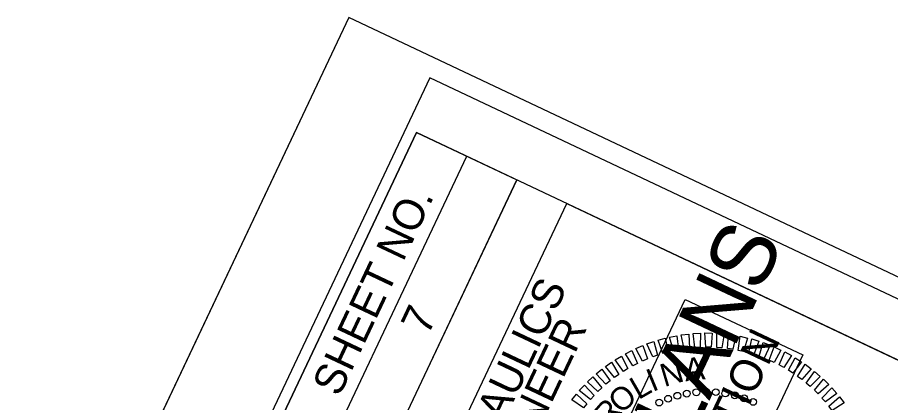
# Model space of a CAD drawing. Extents: x 556536 to 558250, y 505355 to 507347.
# Drawn here: x 557180.4 to 557377.9, y 507260 to 507347.2 of the extents above; entities that cross this region are included whole.
import ezdxf

# ---------------------------------------------------------------- set-up
doc = ezdxf.new("R2010")
doc.units = 0
for name, color, linetype in [('Prop Drainage Structure Box Number Symbol CELL', 7, 'Continuous'), ('Prop Drainage Structure Tops and Inverts LABEL', 7, 'Continuous'), ('Prop Earthen Structure Base Ditch Lateral Detail Label', 7, 'Continuous'), ('Prop Earthen Structure Base Ditch Lateral with Rip Rap Detail Label', 7, 'Continuous'), ('Prop Earthen Structure Berm Ditch Detail Label', 7, 'Continuous'), ('Prop Erosion Rip Rap Class B', 7, 'Continuous'), ('Prop Erosion Rip Rap Pad at Outlet CELL', 7, 'Continuous')]:
    doc.layers.add(name, color=color, linetype=linetype)

msp = doc.modelspace()

# ---------------------------------------------------------------- linework, layer by layer
at = {"layer": 'Prop Drainage Structure Box Number Symbol CELL'}
msp.add_lwpolyline([(557273.74, 507333.49), (556561.61, 505826.81), (557515.52, 505375.94), (558227.66, 506882.62)], close=True, dxfattribs=at)
at = {"layer": 'Prop Drainage Structure Tops and Inverts LABEL'}
msp.add_lwpolyline([(557279.52, 507104.69), (557252.96, 507117.24), (557331.48, 507283.37), (557358.04, 507270.82)], close=True, dxfattribs=at)
at = {"layer": 'Prop Earthen Structure Base Ditch Lateral Detail Label'}
msp.add_lwpolyline([(557255.37, 507347.15), (556535.75, 505824.65), (557530.26, 505354.59), (558249.88, 506877.09)], close=True, dxfattribs=at)
at = {"layer": 'Prop Earthen Structure Berm Ditch Detail Label'}
msp.add_line((557255.37, 507347.15), (556535.75, 505824.65), dxfattribs=at)
at = {"layer": 'Prop Erosion Rip Rap Class B'}
for p, q in [((557196.57, 507134.87), (557282.05, 507315.74)), ((557207.87, 507129.53), (557293.36, 507310.39)), ((557207.87, 507129.53), (557293.36, 507310.39))]:
    msp.add_line(p, q, dxfattribs=at)
for points in [[(557270.71, 507321.1), (556629.72, 505964.95), (557579.02, 505516.26), (558220.01, 506872.41)], [(557185.22, 507140.23), (557270.71, 507321.1), (557293.36, 507310.39), (557207.87, 507129.53)], [(557261.92, 507214.64), (557304.66, 507305.05), (557406.37, 507256.98), (557363.64, 507166.57)]]:
    msp.add_lwpolyline(points, close=True, dxfattribs=at)
at = {"layer": 'Prop Erosion Rip Rap Pad at Outlet CELL'}
for points in [[(557331.23, 507272.19), (557330.57, 507275.35), (557332.24, 507275.54), (557332.4, 507272.35)], [(557333.67, 507272.46), (557333.24, 507275.66), (557334.91, 507275.73), (557334.86, 507272.54)], [(557336.13, 507272.56), (557335.92, 507275.79), (557337.59, 507275.74), (557337.31, 507272.56)], [(557338.59, 507272.49), (557338.6, 507275.72), (557340.27, 507275.56), (557339.77, 507272.4)], [(557341.03, 507272.25), (557341.27, 507275.47), (557342.92, 507275.19), (557342.21, 507272.08)], [(557324.1, 507270.36), (557322.8, 507273.32), (557324.39, 507273.85), (557325.21, 507270.76)], [(557326.43, 507271.14), (557325.34, 507274.18), (557326.96, 507274.6), (557327.57, 507271.46)], [(557328.81, 507271.75), (557327.94, 507274.86), (557329.58, 507275.16), (557329.97, 507271.99)], [(557343.46, 507271.84), (557343.92, 507275.04), (557345.55, 507274.64), (557344.61, 507271.59)], [(557345.85, 507271.26), (557346.53, 507274.42), (557348.13, 507273.91), (557346.98, 507270.93)], [(557348.19, 507270.51), (557349.09, 507273.62), (557350.65, 507273), (557349.3, 507270.1)], [(557319.62, 507268.34), (557317.92, 507271.09), (557319.42, 507271.83), (557320.67, 507268.89)], [(557321.83, 507269.43), (557320.32, 507272.29), (557321.87, 507272.93), (557322.91, 507269.9)], [(557350.47, 507269.61), (557351.59, 507272.64), (557353.1, 507271.92), (557351.55, 507269.12)], [(557352.69, 507268.54), (557354.02, 507271.49), (557355.47, 507270.66), (557353.73, 507267.98)], [(557317.5, 507267.09), (557315.61, 507269.72), (557317.06, 507270.56), (557318.51, 507267.72)], [(557354.83, 507267.33), (557356.36, 507270.18), (557357.75, 507269.25), (557355.83, 507266.7)], [(557313.54, 507264.18), (557311.31, 507266.52), (557312.62, 507267.56), (557314.45, 507264.94)], [(557315.47, 507265.71), (557313.4, 507268.19), (557314.79, 507269.14), (557316.43, 507266.4)], [(557356.87, 507265.97), (557358.6, 507268.7), (557359.92, 507267.68), (557357.83, 507265.27)], [(557311.73, 507262.52), (557309.33, 507264.7), (557310.57, 507265.83), (557312.58, 507263.34)], [(557358.82, 507264.46), (557360.73, 507267.07), (557361.98, 507265.96), (557359.72, 507263.7)], [(557310.03, 507260.75), (557307.49, 507262.75), (557308.65, 507263.96), (557310.83, 507261.62)], [(557360.66, 507262.83), (557362.75, 507265.3), (557363.92, 507264.1), (557361.5, 507262.01)], [(557308.46, 507258.85), (557305.79, 507260.67), (557306.86, 507261.96), (557309.2, 507259.78)], [(557362.38, 507261.07), (557364.63, 507263.39), (557365.72, 507262.11), (557363.16, 507260.19)], [(557363.97, 507259.2), (557366.38, 507261.35), (557367.37, 507260.01), (557364.69, 507258.26)]]:
    msp.add_lwpolyline(points, close=True, dxfattribs=at)
for centre in [(557327.59, 507260.89), (557329.68, 507261.57), (557331.82, 507262.06), (557333.99, 507262.36), (557336.18, 507262.47), (557338.37, 507262.39), (557340.54, 507262.12), (557342.69, 507261.66), (557344.78, 507261.01), (557325.57, 507260.04), (557346.81, 507260.19)]:
    msp.add_circle(centre, 0.777, dxfattribs=at)

# ---------------------------------------------------------------- texts
at = {"layer": 'Prop Drainage Structure Tops and Inverts LABEL'}
for s, height, p in [('INCOMPLETE PLANS', 14.4, (557271.07, 507121.08)), ('DO NOT USE FOR R/W ACQUISITION', 7.2, (557280.66, 507121.04))]:
    msp.add_text(s, height=height, rotation=64.7021, dxfattribs=at).set_placement(p)
at = {"layer": 'Prop Earthen Structure Base Ditch Lateral with Rip Rap Detail Label'}
msp.add_text('7', height=7, rotation=64.7021, dxfattribs=at).set_placement((557273.25, 507274.99))
at = {"layer": 'Prop Erosion Rip Rap Class B'}
for s, p in [('SHEET NO.', (557253.2, 507261.12)), ('HYDRAULICS', (557279.05, 507231.45)), ('ENGINEER', (557288.48, 507232.81))]:
    msp.add_text(s, height=7, rotation=64.7021, dxfattribs=at).set_placement(p)
at = {"layer": 'Prop Erosion Rip Rap Pad at Outlet CELL'}
for s, rotation, p in [('N', 16.469, (557326.72, 507263.53)), ('A', 6.2586, (557331.51, 507264.83)), ('I', 22.4089, (557324.06, 507262.4)), ('L', 29.8741, (557320.91, 507260.59)), ('O', 40.5993, (557316.85, 507257.31)), ('R', 48.8079, (557314.2, 507254.32))]:
    msp.add_text(s, height=5.18, rotation=rotation, dxfattribs=at).set_placement(p)

doc.saveas('drawing.dxf')
